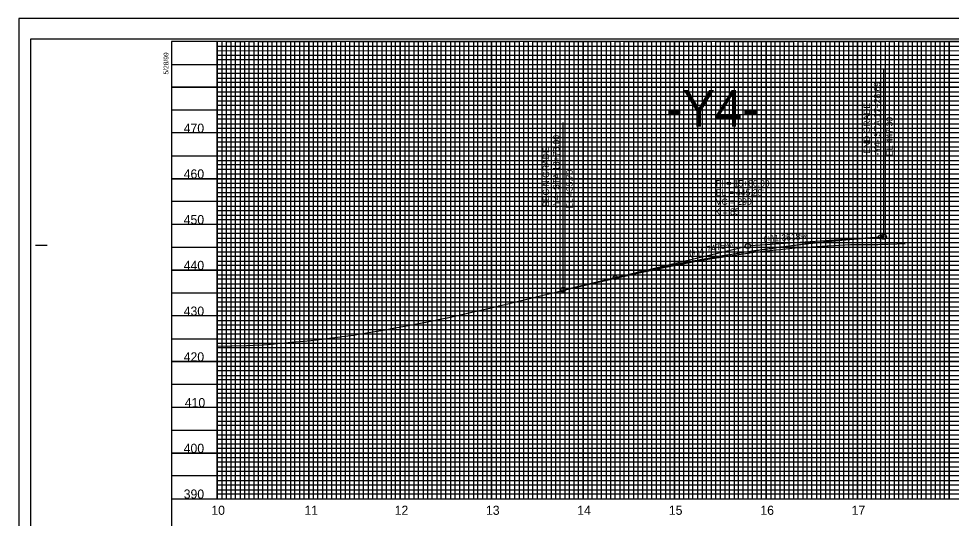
# Model space of a CAD drawing. Extents: x 571503 to 593215, y -77195 to -51828.
# Drawn here: x 582330 to 583349, y -76642 to -76095 of the extents above; entities that cross this region are included whole.
import ezdxf

# ---------------------------------------------------------------- set-up
doc = ezdxf.new("R2010")
doc.units = 0
for name, color, linetype in [('Exist Vertical Profile Ground Line', 7, 'Continuous'), ('Exist Vertical Profile Horizontal Axis Label Major', 7, 'Continuous'), ('Exist Vertical Profile Vertical Axis Label', 7, 'Continuous'), ('Prop PFL Text', 7, 'Continuous'), ('Prop Vertical Profile Curve Label', 7, 'Continuous'), ('Prop Vertical Profile Grade', 7, 'Continuous'), ('Prop Vertical Profile Grade Label', 7, 'Continuous'), ('Prop VPI Label', 7, 'Continuous'), ('Sheet Cutting Line CELL', 7, 'Continuous'), ('Sheet DOT Grid CELL', 7, 'Continuous'), ('Sheet Layout Profile Border Port 1', 7, 'Continuous'), ('Sheet Plot Border Inside CELL', 7, 'Continuous'), ('Sheet Plot Border Outside CELL', 7, 'Continuous'), ('Sheet Profile CELL', 7, 'Continuous'), ('Sheet Profile Grid Major CELL', 7, 'Continuous'), ('Sheet Profile Grid Middle CELL', 7, 'Continuous'), ('Sheet Profile Grid Minor CELL', 7, 'Continuous')]:
    doc.layers.add(name, color=color, linetype=linetype)

msp = doc.modelspace()

# ---------------------------------------------------------------- linework, layer by layer
at = {"layer": 'Exist Vertical Profile Ground Line'}
msp.add_lwpolyline([(582547, -76453.4), (582579, -76452.5), (582579.7, -76452.4), (582596.3, -76451.9), (582597.6, -76451.7), (582628.5, -76449), (582649.5, -76447.1), (582649.6, -76447), (582649.8, -76447), (582678.5, -76443.4), (582681.6, -76443), (582683.1, -76442.7), (582696.3, -76441.1), (582697.9, -76440.9), (582701.7, -76440.3), (582730.1, -76435.3), (582730.6, -76435.3), (582743.2, -76433), (582745.8, -76432.6), (582775.2, -76426.9), (582776.5, -76426.7), (582796.2, -76422.8), (582798.5, -76422.4), (582798.8, -76422.3), (582828.8, -76415.4), (582830.4, -76415), (582854.6, -76409.4), (582854.8, -76409.3), (582855.7, -76409.1), (582886.8, -76401.6), (582909, -76396.2), (582909.4, -76396.1), (582909.5, -76396), (582941.2, -76388.5), (582941.3, -76388.5), (582949.4, -76386.6), (582961.8, -76383.6), (582965.3, -76382.8), (582965.4, -76382.8), (582997.2, -76375.5), (582997.8, -76375.4), (583029.2, -76368.6), (583029.2, -76368.6), (583038.6, -76366.6), (583039.3, -76366.4), (583070.6, -76360.5), (583070.9, -76360.5), (583087.7, -76357.3), (583087.9, -76357.3), (583119.6, -76352.7), (583119.7, -76352.7), (583136.4, -76350.3), (583137, -76350.2), (583168.6, -76347), (583168.7, -76347), (583182.1, -76345.6), (583182.3, -76345.6), (583186.1, -76345.4), (583213.9, -76343.7), (583213.9, -76343.7), (583214.9, -76343.6), (583239.1, -76342.1), (583240, -76342.1), (583269.1, -76342.1), (583271.2, -76341.9), (583276.8, -76341.8), (583277.9, -76341.8), (583278, -76341.8), (583279.1, -76341.8), (583280, -76341.8), (583289.8, -76341.4), (583293.3, -76341.2), (583298.9, -76341.3)], dxfattribs=at)
at = {"layer": 'Prop PFL Text'}
for p, q in [((583275.7, -76333.7), (583275.7, -76150.7)), ((582925, -76391.7), (582925, -76208.7))]:
    msp.add_line(p, q, dxfattribs=at)
at = {"layer": 'Prop Vertical Profile Curve Label'}
for centre in [(583272, -76334), (582982, -76378.2), (582925, -76391.7)]:
    msp.add_circle(centre, 2.25, dxfattribs=at)
at = {"layer": 'Prop Vertical Profile Grade'}
for p, q in [((583272, -76334), (583275.7, -76333.7)), ((582925, -76391.7), (582982, -76378.2))]:
    msp.add_line(p, q, dxfattribs=at)
msp.add_spline([(582982, -76378.2), (582987.8, -76376.8), (582993.6, -76375.5), (582999.4, -76374.2), (583005.2, -76372.8), (583011, -76371.6), (583016.8, -76370.3), (583022.6, -76369), (583028.4, -76367.8), (583034.2, -76366.6), (583040, -76365.4), (583045.8, -76364.2), (583051.6, -76363.1), (583057.4, -76362), (583063.2, -76360.9), (583069, -76359.8), (583074.8, -76358.7), (583080.6, -76357.6), (583086.4, -76356.6), (583092.2, -76355.6), (583098, -76354.6), (583103.8, -76353.6), (583109.6, -76352.7), (583115.4, -76351.7), (583121.2, -76350.8), (583127, -76349.9), (583132.8, -76349.1), (583138.6, -76348.2), (583144.4, -76347.4), (583150.2, -76346.6), (583156, -76345.8), (583161.8, -76345), (583167.6, -76344.2), (583173.4, -76343.5), (583179.2, -76342.8), (583185, -76342.1), (583190.8, -76341.4), (583196.6, -76340.7), (583202.4, -76340.1), (583208.2, -76339.5), (583214, -76338.9), (583219.8, -76338.3), (583225.6, -76337.7), (583231.4, -76337.2), (583237.2, -76336.7), (583243, -76336.2), (583248.8, -76335.7), (583254.6, -76335.2), (583260.4, -76334.8), (583266.2, -76334.4), (583272, -76334)], degree=3, dxfattribs=at)
at = {"layer": 'Prop VPI Label'}
for p, q in [((583272, -76334), (583129.7, -76343.6)), ((582982, -76378.2), (583124.3, -76344.4))]:
    msp.add_line(p, q, dxfattribs=at)
for centre in [(583275.7, -76333.7), (583127, -76343.8), (582925, -76391.7)]:
    msp.add_circle(centre, 2.75, dxfattribs=at)
at = {"layer": 'Sheet Cutting Line CELL'}
for p, q in [((584014, -76095.2), (582330, -76095.2)), ((582330, -76095.2), (582330, -77195.2))]:
    msp.add_line(p, q, dxfattribs=at)
at = {"layer": 'Sheet DOT Grid CELL'}
for p, q in [((582547, -76620.2), (582547, -76120.2)), ((582597, -76620.2), (582597, -76120.2)), ((582647, -76620.2), (582647, -76120.2)), ((582697, -76620.2), (582697, -76120.2)), ((582747, -76620.2), (582747, -76120.2)), ((582797, -76620.2), (582797, -76120.2)), ((582847, -76620.2), (582847, -76120.2)), ((582897, -76620.2), (582897, -76120.2)), ((582947, -76620.2), (582947, -76120.2)), ((582997, -76620.2), (582997, -76120.2)), ((583047, -76620.2), (583047, -76120.2)), ((583097, -76620.2), (583097, -76120.2)), ((583147, -76620.2), (583147, -76120.2)), ((583197, -76620.2), (583197, -76120.2)), ((583247, -76620.2), (583247, -76120.2)), ((583297, -76620.2), (583297, -76120.2)), ((583347, -76620.2), (583347, -76120.2)), ((583796.9, -76170.2), (582497, -76170.2)), ((583796.9, -76220.2), (582497, -76220.2)), ((583997, -76270.2), (582497, -76270.2)), ((583997, -76320.2), (582497, -76320.2)), ((583997, -76370.2), (582497, -76370.2)), ((583997, -76420.2), (582497, -76420.2)), ((583997, -76470.2), (582497, -76470.2)), ((583997, -76520.2), (582497, -76520.2)), ((583997, -76570.2), (582497, -76570.2))]:
    msp.add_line(p, q, dxfattribs=at)
at = {"layer": 'Sheet Layout Profile Border Port 1'}
msp.add_lwpolyline([(582547, -76120.2), (582547, -76620.2), (583947, -76620.2), (583947, -76257.8), (583796.9, -76257.8), (583796.9, -76120.2)], close=True, dxfattribs=at)
at = {"layer": 'Sheet Plot Border Inside CELL'}
msp.add_lwpolyline([(582343, -77172.8), (584009.5, -77172.8), (584009.5, -76117.7), (582343, -76117.7)], close=True, dxfattribs=at)
at = {"layer": 'Sheet Plot Border Outside CELL'}
msp.add_lwpolyline([(582330, -77195.2), (584014, -77195.2), (584014, -76095.2), (582330, -76095.2)], close=True, dxfattribs=at)
at = {"layer": 'Sheet Profile CELL'}
for p, q in [((582348.5, -76342.7), (582361, -76342.7)), ((582497, -76620.2), (583997, -76620.2))]:
    msp.add_line(p, q, dxfattribs=at)
msp.add_lwpolyline([(583997, -76120.2), (582497, -76120.2), (582497, -77170.2), (583997, -77170.2)], close=True, dxfattribs=at)
at = {"layer": 'Sheet Profile Grid Major CELL'}
for points in [[(582547, -76120.2), (582547, -76620.2), (582597, -76620.2), (582597, -76120.2), (582647, -76120.2), (582647, -76620.2), (582697, -76620.2), (582697, -76120.2), (582747, -76120.2), (582747, -76620.2), (582797, -76620.2), (582797, -76120.2), (582847, -76120.2), (582847, -76620.2), (582897, -76620.2), (582897, -76120.2), (582947, -76120.2), (582947, -76620.2), (582997, -76620.2), (582997, -76120.2), (583047, -76120.2), (583047, -76620.2), (583097, -76620.2), (583097, -76120.2), (583147, -76120.2), (583147, -76620.2), (583197, -76620.2), (583197, -76120.2), (583247, -76120.2), (583247, -76620.2), (583297, -76620.2), (583297, -76120.2), (583347, -76120.2), (583347, -76620.2), (583397, -76620.2)], [(582497, -76170.2), (583797, -76170.2)], [(583797, -76220.2), (582497, -76220.2), (582497, -76270.2), (583997, -76270.2)], [(583997, -76320.2), (582497, -76320.2), (582497, -76370.2), (583997, -76370.2)], [(583997, -76420.2), (582497, -76420.2), (582497, -76470.2), (583997, -76470.2)], [(583997, -76520.2), (582497, -76520.2), (582497, -76520.2), (582497, -76570.2), (583997, -76570.2)]]:
    msp.add_lwpolyline(points, dxfattribs=at)
at = {"layer": 'Sheet Profile Grid Middle CELL'}
msp.add_line((582497, -76145.2), (583796.9, -76145.2), dxfattribs=at)
for points in [[(582572, -76120.2), (582572, -76620.2), (582622, -76620.2), (582622, -76120.2), (582672, -76120.2), (582672, -76620.2), (582722, -76620.2), (582722, -76120.2), (582772, -76120.2), (582772, -76620.2), (582822, -76620.2), (582822, -76120.2), (582872, -76120.2), (582872, -76620.2), (582922, -76620.2), (582922, -76120.2), (582972, -76120.2), (582972, -76620.2), (583022, -76620.2), (583022, -76120.2), (583072, -76120.2), (583072, -76620.2), (583122, -76620.2), (583122, -76620.2), (583122, -76120.2), (583172, -76120.2), (583172, -76620.2), (583222, -76620.2), (583222, -76120.2), (583272, -76120.2), (583272, -76620.2), (583322, -76620.2), (583322, -76120.2), (583372, -76120.2)], [(583797, -76195.2), (582497, -76195.2), (582497, -76245.2), (583797, -76245.2)], [(583997, -76295.2), (582497, -76295.2), (582497, -76345.2), (583822, -76345.2)], [(583997, -76395.2), (582497, -76395.2), (582497, -76445.2), (583997, -76445.2)], [(583997, -76495.2), (582497, -76495.2), (582497, -76545.2), (583997, -76545.2)], [(583997, -76595.2), (582497, -76595.2)]]:
    msp.add_lwpolyline(points, dxfattribs=at)
at = {"layer": 'Sheet Profile Grid Minor CELL'}
for p, q in [((582547, -76125.2), (583797, -76125.2)), ((582547, -76130.2), (582547, -76130.2)), ((583797, -76130.2), (582547, -76130.6)), ((582547, -76135.2), (583797, -76135.2)), ((583796.9, -76255.2), (582547, -76255.2)), ((583947, -76260.2), (582547, -76260.2)), ((583947, -76265.2), (582547, -76265.2)), ((582547, -76275.2), (583947, -76275.2)), ((583947, -76280.2), (582547, -76280.2)), ((582547, -76285.2), (583947, -76285.2)), ((583947, -76305.2), (582547, -76305.2)), ((582547, -76310.2), (583947, -76310.2)), ((583947, -76330.2), (582547, -76330.2)), ((582547, -76335.2), (583947, -76335.2)), ((583947, -76355.2), (582547, -76355.2)), ((582547, -76360.2), (583947, -76360.2)), ((583947, -76365.2), (582547, -76365.2)), ((582547, -76375.2), (583947, -76375.2)), ((583947, -76380.2), (582547, -76380.2)), ((582547, -76385.2), (583947, -76385.2)), ((583947, -76390.2), (582547, -76390.2)), ((582547, -76400.2), (583947, -76400.2)), ((583947, -76405.2), (582547, -76405.2)), ((582547, -76410.2), (583947, -76410.2)), ((583947, -76415.2), (582547, -76415.2)), ((582547, -76425.2), (583947, -76425.2)), ((583947, -76430.2), (582547, -76430.2)), ((582547, -76435.2), (583947, -76435.2)), ((583947, -76440.2), (582547, -76440.2)), ((582547, -76450.2), (583947, -76450.2)), ((583947, -76455.2), (582547, -76455.2)), ((582547, -76460.2), (583947, -76460.2)), ((583947, -76465.2), (582547, -76465.2)), ((582547, -76475.2), (583947, -76475.2)), ((583947, -76480.2), (582547, -76480.2)), ((582547, -76485.2), (583947, -76485.2)), ((583947, -76490.2), (582547, -76490.2)), ((582547, -76500.2), (583947, -76500.2)), ((583947, -76505.2), (582547, -76505.2)), ((583947, -76510.2), (582547, -76510.2)), ((583947, -76515.2), (582547, -76515.2)), ((582547, -76525.2), (583947, -76525.2)), ((583947, -76530.2), (582547, -76530.2)), ((582547, -76535.2), (583947, -76535.2)), ((583947, -76540.2), (582547, -76540.2)), ((582547, -76550.2), (583947, -76550.2)), ((583947, -76555.2), (582547, -76555.2)), ((582547, -76560.2), (583947, -76560.2)), ((583947, -76565.2), (582547, -76565.2)), ((582547, -76575.2), (583947, -76575.2)), ((583947, -76580.2), (582547, -76580.2)), ((582547, -76585.2), (583947, -76585.2)), ((583947, -76590.2), (582547, -76590.2)), ((582547, -76600.2), (583947, -76600.2)), ((583947, -76605.2), (582547, -76605.2)), ((582547, -76610.2), (583947, -76610.2))]:
    msp.add_line(p, q, dxfattribs=at)
for points in [[(582552, -76120.2), (582552, -76620.2), (582557, -76620.2), (582557, -76120.2), (582562, -76120.2), (582562, -76620.2), (582567, -76620.2), (582567, -76120.2), (582577, -76120.2), (582577, -76620.2), (582582, -76620.2), (582582, -76120.2), (582587, -76120.2), (582587, -76620.2), (582592, -76620.2), (582602, -76620.2), (582607, -76620.2), (582607, -76120.2), (582612, -76120.2), (582612, -76620.2), (582617, -76620.2), (582617, -76120.2), (582627, -76120.2), (582627, -76620.2), (582632, -76620.2), (582632, -76120.2), (582637, -76120.2), (582637, -76620.2), (582642, -76620.2), (582642, -76120.2), (582652, -76120.2), (582652, -76620.2), (582657, -76620.2), (582657, -76120.2), (582662, -76120.2), (582662, -76620.2), (582667, -76620.2), (582667, -76120.2), (582677, -76120.2), (582677, -76620.2), (582682, -76620.2), (582682, -76120.2), (582687, -76120.2), (582687, -76620.2), (582692, -76620.2), (582692, -76120.2), (582702, -76120.2), (582702, -76620.2), (582707, -76620.2), (582707, -76120.2), (582712, -76120.2), (582712, -76620.2), (582717, -76620.2), (582717, -76120.2), (582727, -76120.2), (582727, -76620.2), (582732, -76620.2), (582732, -76120.2), (582737, -76120.2), (582737, -76620.2), (582742, -76620.2), (582742, -76120.2), (582752, -76120.2), (582752, -76620.2), (582757, -76620.2), (582757, -76120.2), (582762, -76120.2), (582762, -76620.2)], [(582592, -76620.2), (582592, -76120.2), (582602, -76120.2), (582602, -76620.2)], [(582762, -76620.2), (582767, -76620.2), (582767, -76120.2), (582777, -76120.2), (582777, -76620.2), (582782, -76620.2), (582782, -76120.2), (582787, -76120.2), (582787, -76620.2), (582792, -76620.2), (582792, -76120.2), (582802, -76120.2), (582802, -76620.2), (582807, -76620.2), (582807, -76120.2), (582812, -76120.2), (582812, -76620.2), (582817, -76620.2), (582817, -76120.2), (582827, -76120.2), (582827, -76620.2), (582832, -76620.2), (582832, -76120.2), (582837, -76120.2), (582837, -76620.2), (582842, -76620.2), (582842, -76120.2), (582852, -76120.2), (582852, -76620.2), (582857, -76620.2), (582857, -76120.2), (582862, -76120.2), (582862, -76620.2), (582867, -76620.2), (582867, -76120.2), (582877, -76120.2), (582877, -76620.2), (582882, -76620.2), (582882, -76120.2), (582887, -76120.2), (582887, -76620.2), (582892, -76620.2), (582892, -76120.2), (582902, -76120.2), (582902, -76620.2), (582907, -76620.2), (582907, -76120.2), (582912, -76120.2), (582912, -76620.2), (582917, -76620.2), (582917, -76120.2), (582927, -76120.2), (582927, -76620.2), (582932, -76620.2), (582932, -76120.2), (582937, -76120.2), (582937, -76620.2), (582942, -76620.2), (582942, -76120.2), (582952, -76120.2), (582952, -76620.2), (582957, -76620.2), (582957, -76120.2), (582962, -76120.2), (582962, -76620.2), (582967, -76620.2), (582967, -76120.2), (582977, -76120.2), (582977, -76620.2), (582982, -76620.2), (582982, -76120.2), (582987, -76120.2), (582987, -76620.2), (582992, -76620.2), (582992, -76120.2), (583002, -76120.2), (583002, -76620.2), (583007, -76620.2), (583007, -76120.2), (583012, -76120.2), (583012, -76620.2), (583017, -76620.2), (583017, -76120.2), (583027, -76120.2), (583027, -76620.2), (583032, -76620.2), (583032, -76120.2), (583037, -76120.2), (583037, -76620.2), (583042, -76620.2), (583042, -76120.2), (583052, -76120.2), (583052, -76620.2), (583057, -76620.2), (583057, -76120.2), (583062, -76120.2), (583062, -76620.2), (583067, -76620.2), (583067, -76120.2), (583077, -76120.2)], [(583077, -76120.2), (583077, -76620.2), (583082, -76620.2), (583082, -76120.2), (583087, -76120.2), (583087, -76620.2), (583092, -76620.2), (583092, -76120.2), (583102, -76120.2), (583102, -76620.2), (583107, -76620.2), (583107, -76120.2), (583112, -76120.2), (583112, -76620.2), (583117, -76620.2), (583117, -76120.2), (583127, -76120.2), (583127, -76620.2), (583132, -76620.2), (583132, -76120.2), (583137, -76120.2), (583137, -76620.2), (583142, -76620.2), (583142, -76120.2), (583152, -76120.2), (583152, -76620.2), (583157, -76620.2), (583157, -76120.2), (583162, -76120.2), (583162, -76620.2), (583167, -76620.2), (583167, -76120.2), (583177, -76120.2), (583177, -76620.2), (583182, -76620.2), (583182, -76120.2), (583187, -76120.2), (583187, -76620.2), (583192, -76620.2), (583192, -76120.2), (583202, -76120.2), (583202, -76620.2), (583202, -76620.2), (583207, -76620.2), (583207, -76120.2), (583212, -76120.2), (583212, -76620.2), (583217, -76620.2), (583217, -76120.2), (583227, -76120.2), (583227, -76620.2), (583232, -76620.2), (583232, -76120.2), (583237, -76120.2), (583237, -76620.2), (583242, -76620.2), (583242, -76120.2), (583252, -76120.2), (583252, -76620.2), (583257, -76620.2), (583257, -76120.2), (583262, -76120.2), (583262, -76620.2), (583267, -76620.2), (583267, -76120.2), (583277, -76120.2), (583277, -76620.2), (583282, -76620.2), (583282, -76120.2), (583287, -76120.2), (583287, -76620.2), (583292, -76620.2), (583292, -76120.2), (583302, -76120.2), (583302, -76620.2), (583307, -76620.2), (583307, -76120.2), (583312, -76120.2), (583312, -76620.2), (583317, -76620.2), (583317, -76120.2), (583327, -76120.2), (583327, -76620.2), (583332, -76620.2), (583332, -76120.2), (583337, -76120.2), (583337, -76620.2), (583342, -76620.2), (583342, -76120.2), (583352, -76120.2)], [(583797, -76140.2), (582547, -76140.2), (582547, -76150.2), (583797, -76150.2)], [(583796.9, -76155.2), (582547, -76155.2), (582547, -76160.2), (583797, -76160.2)], [(583797, -76165.2), (582547, -76165.2), (582547, -76175.2), (583797, -76175.2)], [(583797, -76180.2), (582547, -76180.2), (582547, -76185.2), (583797, -76185.2)], [(583797, -76190.2), (582547, -76190.2), (582547, -76200.2), (583797, -76200.2)], [(583797, -76205.2), (582547, -76205.2), (582547, -76210.2), (583797, -76210.2)], [(583797, -76215.2), (582547, -76215.2), (582547, -76225.2), (583797, -76225.2)], [(583797, -76230.3), (582547.1, -76230.3), (582547.1, -76235.2), (583797, -76235.2)], [(583797, -76240.2), (582547, -76240.2), (582547, -76250.2), (583797, -76250.2)], [(583947, -76290.2), (582547, -76290.2), (582547, -76300.2), (583947, -76300.2)], [(583947, -76315.2), (582547, -76315.2), (582547, -76325.2), (583947, -76325.2)], [(583947, -76340.2), (582547, -76340.2), (582547, -76350.2), (583947, -76350.2)], [(583947, -76615.2), (582547, -76615.2)]]:
    msp.add_lwpolyline(points, dxfattribs=at)

# ---------------------------------------------------------------- texts
at = {"layer": 'Exist Vertical Profile Horizontal Axis Label Major'}
for s, p in [('10', (582540.6, -76637.7)), ('11', (582642.4, -76637.7)), ('12', (582741, -76637.7)), ('13', (582840.8, -76637.7)), ('14', (582940.6, -76637.7)), ('15', (583040.7, -76637.7)), ('16', (583140.7, -76637.7)), ('17', (583240.5, -76637.7))]:
    msp.add_text(s, height=10, dxfattribs=at).set_placement(p)
at = {"layer": 'Exist Vertical Profile Vertical Axis Label'}
for s, height, p in [('-Y4-', 40, (583037.7, -76213.4)), ('470', 10, (582510.4, -76220)), ('460', 10, (582510.4, -76270)), ('450', 10, (582510.4, -76320)), ('440', 10, (582510.4, -76370)), ('430', 10, (582510.4, -76420)), ('420', 10, (582510.4, -76470)), ('410', 10, (582511.6, -76520)), ('400', 10, (582510.4, -76570)), ('390', 10, (582510.4, -76620))]:
    msp.add_text(s, height=height, dxfattribs=at).set_placement(p)
at = {"layer": 'Prop PFL Text'}
for s, p in [('-Y4- STA 17+28.69', (583271.8, -76244.8)), ('END GRADE', (583260.5, -76243)), ('EL 447.30', (583285.3, -76245.4)), ('-Y4- STA 13+78.00', (582921.1, -76302.8)), ('BEGIN GRADE', (582909.8, -76301)), ('EL 435.70', (582935.6, -76303.1))]:
    msp.add_text(s, height=7, rotation=90, dxfattribs=at).set_placement(p)
at = {"layer": 'Prop Vertical Profile Curve Label'}
for s, p in [("VC = 290'", (583092, -76298.8)), ('K = 85', (583090.7, -76309.7))]:
    msp.add_text(s, height=7, dxfattribs=at).set_placement(p)
at = {"layer": 'Prop Vertical Profile Grade Label'}
for s, rotation, p in [('(+)1.3518%', 3.8668, (583144.5, -76339.6)), ('(+)4.7475%', 13.3535, (583063.7, -76355.7))]:
    msp.add_text(s, height=7, rotation=rotation, dxfattribs=at).set_placement(p)
at = {"layer": 'Prop VPI Label'}
for s, p in [('PI = 15+80.00', (583092, -76278.8)), ("EL = 445.29'", (583092, -76288.8))]:
    msp.add_text(s, height=7, dxfattribs=at).set_placement(p)
at = {"layer": 'Sheet Profile CELL'}
msp.add_text('5/28/99', height=5.25, rotation=90, dxfattribs=at).set_placement((582493.7, -76156.3))

doc.saveas('drawing.dxf')
